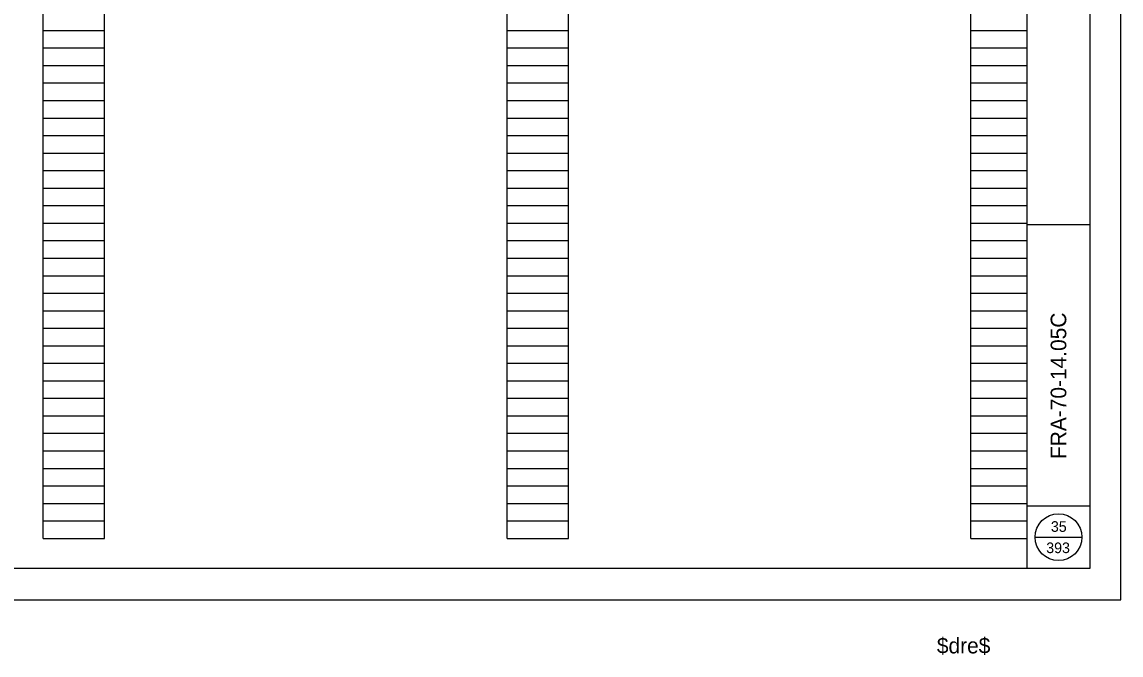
# Model space of a CAD drawing. Extents: x 1835969 to 1838545, y 714903 to 716193.
# Drawn here: x 1836019.22 to 1836036.8, y 714960.53 to 714970.64 of the extents above; entities that cross this region are included whole.
import ezdxf

# ---------------------------------------------------------------- set-up
doc = ezdxf.new("R2010")
doc.units = 0
for name, color, linetype in [('SC_Scratch2', 7, 'Continuous'), ('SH_Border', 7, 'Continuous'), ('SH_Cut_Line', 7, 'Continuous'), ('SH_Data', 7, 'Continuous')]:
    doc.layers.add(name, color=color, linetype=linetype)

msp = doc.modelspace()

# ---------------------------------------------------------------- linework, layer by layer
at = {"layer": 'SC_Scratch2'}
for p, q in [((1836019.561, 714962.39), (1836019.561, 714982.55)), ((1836020.541, 714962.39), (1836020.541, 714982.55)), ((1836026.981, 714962.39), (1836026.981, 714982.55)), ((1836027.961, 714962.39), (1836027.961, 714982.55)), ((1836034.401, 714962.39), (1836034.401, 714982.55)), ((1836035.301, 714962.39), (1836035.301, 714982.55)), ((1836019.561, 714970.51), (1836020.541, 714970.51)), ((1836026.981, 714970.51), (1836027.961, 714970.51)), ((1836034.401, 714970.51), (1836035.301, 714970.51)), ((1836019.561, 714970.23), (1836020.541, 714970.23)), ((1836026.981, 714970.23), (1836027.961, 714970.23)), ((1836034.401, 714970.23), (1836035.301, 714970.23)), ((1836019.561, 714969.95), (1836020.541, 714969.95)), ((1836026.981, 714969.95), (1836027.961, 714969.95)), ((1836034.401, 714969.95), (1836035.301, 714969.95)), ((1836019.561, 714969.67), (1836020.541, 714969.67)), ((1836026.981, 714969.67), (1836027.961, 714969.67)), ((1836034.401, 714969.67), (1836035.301, 714969.67)), ((1836019.561, 714969.39), (1836020.541, 714969.39)), ((1836026.981, 714969.39), (1836027.961, 714969.39)), ((1836034.401, 714969.39), (1836035.301, 714969.39)), ((1836019.561, 714969.11), (1836020.541, 714969.11)), ((1836026.981, 714969.11), (1836027.961, 714969.11)), ((1836034.401, 714969.11), (1836035.301, 714969.11)), ((1836019.561, 714968.83), (1836020.541, 714968.83)), ((1836026.981, 714968.83), (1836027.961, 714968.83)), ((1836034.401, 714968.83), (1836035.301, 714968.83)), ((1836019.561, 714968.55), (1836020.541, 714968.55)), ((1836026.981, 714968.55), (1836027.961, 714968.55)), ((1836034.401, 714968.55), (1836035.301, 714968.55)), ((1836019.561, 714968.27), (1836020.541, 714968.27)), ((1836026.981, 714968.27), (1836027.961, 714968.27)), ((1836034.401, 714968.27), (1836035.301, 714968.27)), ((1836019.561, 714967.99), (1836020.541, 714967.99)), ((1836026.981, 714967.99), (1836027.961, 714967.99)), ((1836034.401, 714967.99), (1836035.301, 714967.99)), ((1836019.561, 714967.71), (1836020.541, 714967.71)), ((1836026.981, 714967.71), (1836027.961, 714967.71)), ((1836034.401, 714967.71), (1836035.301, 714967.71)), ((1836019.561, 714967.43), (1836020.541, 714967.43)), ((1836026.981, 714967.43), (1836027.961, 714967.43)), ((1836034.401, 714967.43), (1836035.301, 714967.43)), ((1836019.561, 714967.15), (1836020.541, 714967.15)), ((1836026.981, 714967.15), (1836027.961, 714967.15)), ((1836034.401, 714967.15), (1836035.301, 714967.15)), ((1836019.561, 714966.87), (1836020.541, 714966.87)), ((1836026.981, 714966.87), (1836027.961, 714966.87)), ((1836034.401, 714966.87), (1836035.301, 714966.87)), ((1836019.561, 714966.59), (1836020.541, 714966.59)), ((1836026.981, 714966.59), (1836027.961, 714966.59)), ((1836034.401, 714966.59), (1836035.301, 714966.59)), ((1836019.561, 714966.31), (1836020.541, 714966.31)), ((1836026.981, 714966.31), (1836027.961, 714966.31)), ((1836034.401, 714966.31), (1836035.301, 714966.31)), ((1836019.561, 714966.03), (1836020.541, 714966.03)), ((1836026.981, 714966.03), (1836027.961, 714966.03)), ((1836034.401, 714966.03), (1836035.301, 714966.03)), ((1836019.561, 714965.75), (1836020.541, 714965.75)), ((1836026.981, 714965.75), (1836027.961, 714965.75)), ((1836034.401, 714965.75), (1836035.301, 714965.75)), ((1836019.561, 714965.47), (1836020.541, 714965.47)), ((1836026.981, 714965.47), (1836027.961, 714965.47)), ((1836034.401, 714965.47), (1836035.301, 714965.47)), ((1836019.561, 714965.19), (1836020.541, 714965.19)), ((1836026.981, 714965.19), (1836027.961, 714965.19)), ((1836034.401, 714965.19), (1836035.301, 714965.19)), ((1836019.561, 714964.91), (1836020.541, 714964.91)), ((1836026.981, 714964.91), (1836027.961, 714964.91)), ((1836034.401, 714964.91), (1836035.301, 714964.91)), ((1836019.561, 714964.63), (1836020.541, 714964.63)), ((1836026.981, 714964.63), (1836027.961, 714964.63)), ((1836034.401, 714964.63), (1836035.301, 714964.63)), ((1836019.561, 714964.35), (1836020.541, 714964.35)), ((1836026.981, 714964.35), (1836027.961, 714964.35)), ((1836034.401, 714964.35), (1836035.301, 714964.35)), ((1836019.561, 714964.07), (1836020.541, 714964.07)), ((1836026.981, 714964.07), (1836027.961, 714964.07)), ((1836034.401, 714964.07), (1836035.301, 714964.07)), ((1836019.561, 714963.79), (1836020.541, 714963.79)), ((1836026.981, 714963.79), (1836027.961, 714963.79)), ((1836034.401, 714963.79), (1836035.301, 714963.79)), ((1836019.561, 714963.51), (1836020.541, 714963.51)), ((1836026.981, 714963.51), (1836027.961, 714963.51)), ((1836034.401, 714963.51), (1836035.301, 714963.51)), ((1836019.561, 714963.23), (1836020.541, 714963.23)), ((1836026.981, 714963.23), (1836027.961, 714963.23)), ((1836034.401, 714963.23), (1836035.301, 714963.23)), ((1836019.561, 714962.95), (1836020.541, 714962.95)), ((1836026.981, 714962.95), (1836027.961, 714962.95)), ((1836034.401, 714962.95), (1836035.301, 714962.95)), ((1836019.561, 714962.67), (1836020.541, 714962.67)), ((1836026.981, 714962.67), (1836027.961, 714962.67)), ((1836034.401, 714962.67), (1836035.301, 714962.67)), ((1836019.561, 714962.39), (1836020.541, 714962.39)), ((1836026.981, 714962.39), (1836027.961, 714962.39)), ((1836034.401, 714962.39), (1836035.301, 714962.39))]:
    msp.add_line(p, q, dxfattribs=at)
at = {"layer": 'SH_Border'}
for p, q in [((1836035.301, 714961.91), (1836035.301, 714982.91)), ((1836035.301, 714967.41), (1836036.301, 714967.41)), ((1836035.301, 714962.91), (1836036.301, 714962.91))]:
    msp.add_line(p, q, dxfattribs=at)
msp.add_lwpolyline([(1836004.801, 714982.91), (1836036.301, 714982.91), (1836036.301, 714961.91), (1836004.801, 714961.91)], close=True, dxfattribs=at)
at = {"layer": 'SH_Cut_Line'}
msp.add_lwpolyline([(1836002.801, 714961.41), (1836036.801, 714961.41), (1836036.801, 714983.41), (1836002.801, 714983.41)], close=True, dxfattribs=at)
at = {"layer": 'SH_Data'}
for p, q in [((1836019.561, 714962.39), (1836019.561, 714982.55)), ((1836020.541, 714962.39), (1836020.541, 714982.55)), ((1836026.981, 714962.39), (1836026.981, 714982.55)), ((1836027.961, 714962.39), (1836027.961, 714982.55)), ((1836034.401, 714962.39), (1836034.401, 714982.55)), ((1836035.301, 714962.39), (1836035.301, 714982.55)), ((1836019.561, 714970.51), (1836020.541, 714970.51)), ((1836026.981, 714970.51), (1836027.961, 714970.51)), ((1836034.401, 714970.51), (1836035.301, 714970.51)), ((1836019.561, 714970.23), (1836020.541, 714970.23)), ((1836026.981, 714970.23), (1836027.961, 714970.23)), ((1836034.401, 714970.23), (1836035.301, 714970.23)), ((1836019.561, 714969.95), (1836020.541, 714969.95)), ((1836026.981, 714969.95), (1836027.961, 714969.95)), ((1836034.401, 714969.95), (1836035.301, 714969.95)), ((1836019.561, 714969.67), (1836020.541, 714969.67)), ((1836026.981, 714969.67), (1836027.961, 714969.67)), ((1836034.401, 714969.67), (1836035.301, 714969.67)), ((1836019.561, 714969.39), (1836020.541, 714969.39)), ((1836026.981, 714969.39), (1836027.961, 714969.39)), ((1836034.401, 714969.39), (1836035.301, 714969.39)), ((1836019.561, 714969.11), (1836020.541, 714969.11)), ((1836026.981, 714969.11), (1836027.961, 714969.11)), ((1836034.401, 714969.11), (1836035.301, 714969.11)), ((1836019.561, 714968.83), (1836020.541, 714968.83)), ((1836026.981, 714968.83), (1836027.961, 714968.83)), ((1836034.401, 714968.83), (1836035.301, 714968.83)), ((1836019.561, 714968.55), (1836020.541, 714968.55)), ((1836026.981, 714968.55), (1836027.961, 714968.55)), ((1836034.401, 714968.55), (1836035.301, 714968.55)), ((1836019.561, 714968.27), (1836020.541, 714968.27)), ((1836026.981, 714968.27), (1836027.961, 714968.27)), ((1836034.401, 714968.27), (1836035.301, 714968.27)), ((1836019.561, 714967.99), (1836020.541, 714967.99)), ((1836026.981, 714967.99), (1836027.961, 714967.99)), ((1836034.401, 714967.99), (1836035.301, 714967.99)), ((1836019.561, 714967.71), (1836020.541, 714967.71)), ((1836026.981, 714967.71), (1836027.961, 714967.71)), ((1836034.401, 714967.71), (1836035.301, 714967.71)), ((1836019.561, 714967.43), (1836020.541, 714967.43)), ((1836026.981, 714967.43), (1836027.961, 714967.43)), ((1836034.401, 714967.43), (1836035.301, 714967.43)), ((1836019.561, 714967.15), (1836020.541, 714967.15)), ((1836026.981, 714967.15), (1836027.961, 714967.15)), ((1836034.401, 714967.15), (1836035.301, 714967.15)), ((1836019.561, 714966.87), (1836020.541, 714966.87)), ((1836026.981, 714966.87), (1836027.961, 714966.87)), ((1836034.401, 714966.87), (1836035.301, 714966.87)), ((1836019.561, 714966.59), (1836020.541, 714966.59)), ((1836026.981, 714966.59), (1836027.961, 714966.59)), ((1836034.401, 714966.59), (1836035.301, 714966.59)), ((1836019.561, 714966.31), (1836020.541, 714966.31)), ((1836026.981, 714966.31), (1836027.961, 714966.31)), ((1836034.401, 714966.31), (1836035.301, 714966.31)), ((1836019.561, 714966.03), (1836020.541, 714966.03)), ((1836026.981, 714966.03), (1836027.961, 714966.03)), ((1836034.401, 714966.03), (1836035.301, 714966.03)), ((1836019.561, 714965.75), (1836020.541, 714965.75)), ((1836026.981, 714965.75), (1836027.961, 714965.75)), ((1836034.401, 714965.75), (1836035.301, 714965.75)), ((1836019.561, 714965.47), (1836020.541, 714965.47)), ((1836026.981, 714965.47), (1836027.961, 714965.47)), ((1836034.401, 714965.47), (1836035.301, 714965.47)), ((1836019.561, 714965.19), (1836020.541, 714965.19)), ((1836026.981, 714965.19), (1836027.961, 714965.19)), ((1836034.401, 714965.19), (1836035.301, 714965.19)), ((1836019.561, 714964.91), (1836020.541, 714964.91)), ((1836026.981, 714964.91), (1836027.961, 714964.91)), ((1836034.401, 714964.91), (1836035.301, 714964.91)), ((1836019.561, 714964.63), (1836020.541, 714964.63)), ((1836026.981, 714964.63), (1836027.961, 714964.63)), ((1836034.401, 714964.63), (1836035.301, 714964.63)), ((1836019.561, 714964.35), (1836020.541, 714964.35)), ((1836026.981, 714964.35), (1836027.961, 714964.35)), ((1836034.401, 714964.35), (1836035.301, 714964.35)), ((1836019.561, 714964.07), (1836020.541, 714964.07)), ((1836026.981, 714964.07), (1836027.961, 714964.07)), ((1836034.401, 714964.07), (1836035.301, 714964.07)), ((1836019.561, 714963.79), (1836020.541, 714963.79)), ((1836026.981, 714963.79), (1836027.961, 714963.79)), ((1836034.401, 714963.79), (1836035.301, 714963.79)), ((1836019.561, 714963.51), (1836020.541, 714963.51)), ((1836026.981, 714963.51), (1836027.961, 714963.51)), ((1836034.401, 714963.51), (1836035.301, 714963.51)), ((1836019.561, 714963.23), (1836020.541, 714963.23)), ((1836026.981, 714963.23), (1836027.961, 714963.23)), ((1836034.401, 714963.23), (1836035.301, 714963.23)), ((1836019.561, 714962.95), (1836020.541, 714962.95)), ((1836026.981, 714962.95), (1836027.961, 714962.95)), ((1836034.401, 714962.95), (1836035.301, 714962.95)), ((1836019.561, 714962.67), (1836020.541, 714962.67)), ((1836026.981, 714962.67), (1836027.961, 714962.67)), ((1836034.401, 714962.67), (1836035.301, 714962.67)), ((1836019.561, 714962.39), (1836020.541, 714962.39)), ((1836026.981, 714962.39), (1836027.961, 714962.39)), ((1836034.401, 714962.39), (1836035.301, 714962.39)), ((1836035.426, 714962.41), (1836036.176, 714962.41))]:
    msp.add_line(p, q, dxfattribs=at)
msp.add_circle((1836035.801, 714962.41), 0.375, dxfattribs=at)

# ---------------------------------------------------------------- texts
msp.add_text('FRA-70-14.05C', height=0.25, rotation=90, dxfattribs=at).set_placement((1836035.926, 714963.659))
for s, height, p in [('35', 0.17, (1836035.68, 714962.495)), ('393', 0.17, (1836035.605, 714962.155)), ('$dre$', 0.25, (1836033.856, 714960.552))]:
    msp.add_text(s, height=height, dxfattribs=at).set_placement(p)

doc.saveas('drawing.dxf')
